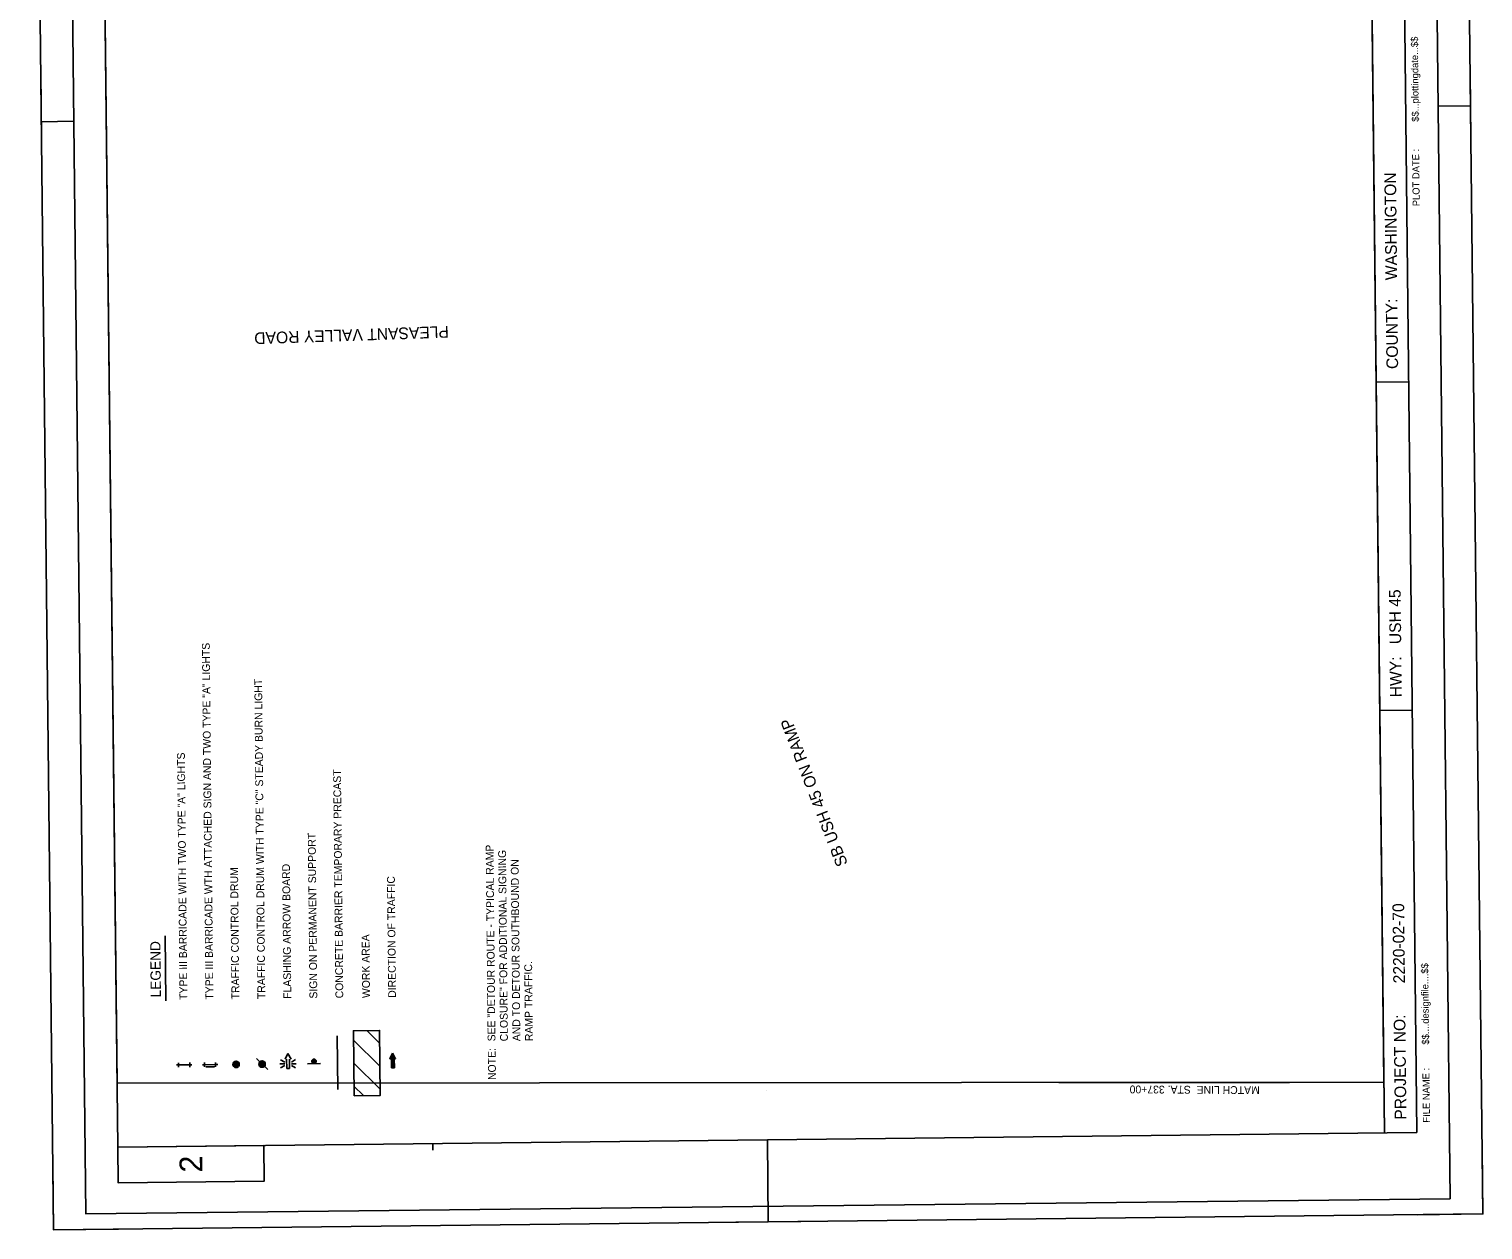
# Model space of a CAD drawing. Extents: x 359329 to 360448, y 158019 to 159731.
# Drawn here: x 359329 to 360448, y 158019 to 158943 of the extents above; entities that cross this region are included whole.
import ezdxf

# ---------------------------------------------------------------- set-up
doc = ezdxf.new("R2010")
doc.units = 0
for name, color, linetype in [('CA-MTCH-LINE', 7, 'Continuous'), ('CA-MTCH-LINE-TEXT', 7, 'Continuous'), ('Default', 7, 'Continuous'), ('Level 28', 7, 'Continuous'), ('P_Kapur_PFFE CELL [KAPUR_CADDS_LEVELS]', 7, 'Continuous'), ('P_MISC', 7, 'Continuous'), ('P_RDWY_Text', 7, 'Continuous'), ('P_TC', 7, 'Continuous'), ('P_TC_FlowArrow', 7, 'Continuous'), ('P_TC_Text', 7, 'Continuous'), ('P_TXT_Plan 1 [KAPUR_CADDS_LEVELS]', 7, 'Continuous'), ('PLT_Sheet_Info', 7, 'Continuous')]:
    doc.layers.add(name, color=color, linetype=linetype)

msp = doc.modelspace()

# ---------------------------------------------------------------- linework, layer by layer
at = {"layer": 'CA-MTCH-LINE'}
msp.add_line((360121.1, 158132.3), (360298.8, 158132.4), dxfattribs=at)
at = {"layer": 'Default'}
msp.add_lwpolyline([(359396.4, 158131.7), (360371.4, 158132.5), (360354.3, 159668.5), (359606.5, 159660.2), (359611.2, 159267.1), (359383.8, 159264.8)], close=True, dxfattribs=at)
msp.add_lwpolyline([(359396.4, 158131.7), (360371.4, 158132.5), (360354.3, 159668.5), (359606.5, 159660.2), (359611.2, 159267.1), (359383.8, 159264.8)], close=True, dxfattribs=at)
msp.add_lwpolyline([(359396.4, 158131.7), (360371.4, 158132.5), (360354.3, 159668.5), (359606.5, 159660.2), (359611.2, 159267.1), (359383.8, 159264.8)], close=True, dxfattribs=at)
at = {"layer": 'Level 28'}
for p, q in [((360371.8, 158093.6), (360354.3, 159668.5)), ((360396.8, 158093.9), (360379.3, 159668.8)), ((359396.9, 158082.7), (359379.4, 159657.6)), ((360438.3, 158858.6), (360437.8, 158908.6)), ((359338.4, 158846.4), (359337.9, 158896.4)), ((360438.1, 158883.6), (360413.1, 158883.3)), ((359338.1, 158871.4), (359363.1, 158871.7)), ((360390.4, 158671.3), (360365.4, 158671)), ((360393.2, 158418.8), (360368.2, 158418.6)), ((359896.5, 158125.8), (359896.5, 158125.8)), ((360396.8, 158093.9), (359396.9, 158082.7)), ((359639.4, 158085.4), (359639.4, 158080.4)), ((359897.6, 158025.1), (359896.9, 158088.3)), ((360447.5, 158031.2), (360447, 158081.2)), ((359347.6, 158018.9), (359347.1, 158068.9)), ((359922.6, 158025.3), (359872.6, 158024.8)), ((360447.5, 158031.2), (360397.5, 158030.6)), ((359397.6, 158019.5), (359347.6, 158018.9))]:
    msp.add_line(p, q, dxfattribs=at)
msp.add_lwpolyline([(359396.9, 158082.7), (359397.2, 158055.2), (359509.7, 158056.5), (359509.4, 158084)], close=True, dxfattribs=at)
at = {"layer": 'P_Kapur_PFFE CELL [KAPUR_CADDS_LEVELS]'}
for points in [[(360447.5, 158031.2), (360428.6, 159731.1), (359328.7, 159718.8), (359347.6, 158018.9)], [(360422.4, 158042.9), (360404, 159697.8), (359354.1, 159686.1), (359372.5, 158031.2)]]:
    msp.add_lwpolyline(points, close=True, dxfattribs=at)
at = {"layer": 'P_MISC'}
for p, q in [((359598.5, 158162.7), (359588.7, 158172.3)), ((359598.6, 158145), (359578.4, 158164.9)), ((359443.8, 158145.8), (359443.8, 158147.5)), ((359443.8, 158147.5), (359443.8, 158145.8)), ((359452.3, 158147.6), (359452.3, 158145.9)), ((359452.3, 158145.9), (359452.3, 158147.6)), ((359463.8, 158146), (359463.8, 158147.7)), ((359463.8, 158147.7), (359463.8, 158146)), ((359472.3, 158147.8), (359472.3, 158146.1)), ((359472.3, 158146.1), (359472.3, 158147.8)), ((359472.3, 158146.1), (359474, 158146.1)), ((359474, 158146.1), (359472.3, 158146.1)), ((359512.4, 158142.3), (359503.7, 158150.7)), ((359525.5, 158146.7), (359521.8, 158146.6)), ((359525.5, 158147.9), (359522.3, 158149.8)), ((359525.8, 158150.2), (359527.9, 158154.6)), ((359527, 158143.1), (359526.9, 158150.2)), ((359527.9, 158154.6), (359530.3, 158150.3)), ((359529.1, 158150.3), (359529.2, 158143.1)), ((359530.6, 158148), (359533.8, 158149.9)), ((359530.6, 158146.7), (359534.3, 158146.8)), ((359553, 158146.9), (359543, 158146.8)), ((359598.8, 158127.3), (359578.6, 158147.2)), ((359443.8, 158145.8), (359442.1, 158145.8)), ((359442.1, 158145.8), (359443.8, 158145.8)), ((359452.3, 158145.9), (359443.8, 158145.8)), ((359443.8, 158145.8), (359443.8, 158144.1)), ((359443.8, 158144.1), (359443.8, 158145.8)), ((359452.3, 158145.9), (359454, 158145.9)), ((359454, 158145.9), (359452.3, 158145.9)), ((359452.3, 158145.9), (359452.3, 158144.2)), ((359452.3, 158144.2), (359452.3, 158145.9)), ((359463.8, 158146), (359462.1, 158146)), ((359462.1, 158146), (359463.8, 158146)), ((359472.3, 158146.1), (359463.8, 158146)), ((359463.8, 158146), (359463.8, 158144.3)), ((359463.8, 158144.3), (359463.8, 158146)), ((359471.3, 158144.4), (359464.8, 158144.4)), ((359472.3, 158146.1), (359472.3, 158144.4)), ((359472.3, 158144.4), (359472.3, 158146.1)), ((359525.5, 158145.4), (359522.3, 158143.5)), ((359529.2, 158143.1), (359527, 158143.1)), ((359530.6, 158145.5), (359533.8, 158143.6)), ((359586.1, 158122.3), (359578.7, 158129.5))]:
    msp.add_line(p, q, dxfattribs=at)
msp.add_lwpolyline([(359578.8, 158122.2), (359578.3, 158172.2), (359598.4, 158172.4), (359598.9, 158122.4)], close=True, dxfattribs=at)
for centre, radius in [((359488, 158146.3), 2.5), ((359488, 158146.3), 2), ((359488, 158146.3), 1.5), ((359488, 158146.3), 1), ((359488, 158146.3), 0.5), ((359488, 158146.3), 0.25), ((359508, 158146.5), 2.5), ((359508, 158146.5), 2), ((359508, 158146.5), 1.5), ((359508, 158146.5), 1), ((359508, 158146.5), 0.5), ((359508, 158146.5), 0.25), ((359548, 158148.6), 1.75), ((359548, 158148.6), 1), ((359548, 158148.6), 0.25)]:
    msp.add_circle(centre, radius, dxfattribs=at)
at = {"layer": 'P_RDWY_Text'}
msp.add_lwpolyline([(359347.6, 158018.9), (359328.7, 159718.8), (360428.6, 159731.1), (360447.5, 158031.2)], close=True, dxfattribs=at)
at = {"layer": 'P_TC'}
for p, q in [((359608.5, 158155), (359606.3, 158150.6)), ((359606.3, 158150.6), (359610.8, 158150.6)), ((359606.6, 158150.6), (359606.6, 158151)), ((359607, 158150.6), (359607, 158151.9)), ((359607.5, 158150.6), (359607.5, 158152.8)), ((359607.5, 158143.5), (359607.5, 158150.6)), ((359608, 158143.5), (359607.9, 158153.7)), ((359608.4, 158143.5), (359608.3, 158154.6)), ((359608.5, 158155), (359610.8, 158150.6)), ((359608.9, 158143.5), (359608.8, 158154.5)), ((359609.3, 158143.5), (359609.2, 158153.6)), ((359609.7, 158150.6), (359609.7, 158152.8)), ((359609.8, 158143.5), (359609.7, 158150.6)), ((359610.2, 158150.6), (359610.2, 158151.9)), ((359610.6, 158150.7), (359610.6, 158151.1)), ((359607.5, 158143.5), (359609.8, 158143.5)), ((359608.7, 158143.5), (359608.7, 158143.5))]:
    msp.add_line(p, q, dxfattribs=at)
at = {"layer": 'P_TC_FlowArrow'}
msp.add_line((359566.3, 158126.9), (359565.8, 158168.3), dxfattribs=at)
at = {"layer": 'P_TC_Text'}
msp.add_line((359434, 158195.2), (359433.5, 158245.1), dxfattribs=at)
at = {"layer": 'P_TXT_Plan 1 [KAPUR_CADDS_LEVELS]'}
msp.add_lwpolyline([(359347.6, 158018.9), (359328.7, 159718.8), (360428.6, 159731.1), (360447.5, 158031.2), (359347.6, 158018.9)], dxfattribs=at)
at = {"layer": 'PLT_Sheet_Info'}
msp.add_lwpolyline([(360371.8, 158093.6), (360354.3, 159668.5)], dxfattribs=at)

# ---------------------------------------------------------------- texts
at = {"layer": 'CA-MTCH-LINE-TEXT'}
for s, height, rotation, p in [('PLEASANT VALLEY ROAD', 9, 181.9355, (359651.6, 158714.3)), ('SB USH 45 ON RAMP', 9, 111.2195, (359958.9, 158300.6)), ('MATCH LINE  STA. 337+00', 6, 179.6332, (360275.8, 158129.4))]:
    msp.add_text(s, height=height, rotation=rotation, dxfattribs=at).set_placement(p)
at = {"layer": 'Level 28'}
for s, height, p in [('$$...plottingdate...$$', 5.4, (360398.2, 158871.4)), ('PLOT DATE :', 5.4, (360398.9, 158806.4)), (' WASHINGTON', 9, (360381.6, 158746.2)), ('COUNTY:', 9, (360382.3, 158681.2)), (' USH 45', 9, (360384.7, 158466.2)), ('HWY:', 9, (360385.1, 158428.7)), (' 2220-02-70', 9, (360387.6, 158205.3)), ('$$....designfile....$$', 5.4, (360406.1, 158161.5)), ('PROJECT NO:', 9, (360388.7, 158103.8)), ('FILE NAME :', 5.4, (360406.8, 158101.5)), ('2', 17.5, (359462.1, 158063.2))]:
    msp.add_text(s, height=height, rotation=90.6368, dxfattribs=at).set_placement(p)
at = {"layer": 'P_TC_Text'}
for s, height, p in [('TYPE III BARRICADE WTH ATTACHED SIGN AND TWO TYPE "A" LIGHTS', 6, (359470.5, 158196.1)), ('TRAFFIC CONTROL DRUM WITH TYPE "C" STEADY BURN LIGHT', 6, (359510.5, 158196.5)), ('TYPE III BARRICADE WITH TWO TYPE "A" LIGHTS', 6, (359450.5, 158195.9)), ('CONCRETE BARRIER TEMPORARY PRECAST', 6, (359570.5, 158197.1)), ('SIGN ON PERMANENT SUPPORT', 6, (359550.5, 158196.9)), ('SEE "DETOUR ROUTE - TYPICAL RAMP', 6, (359687.6, 158164)), ('CLOSURE" FOR ADDITIONAL SIGNING', 6, (359697.2, 158164)), ('AND TO DETOUR SOUTHBOUND ON', 6, (359706.8, 158164.1)), ('TRAFFIC CONTROL DRUM', 6, (359490.5, 158196.3)), ('FLASHING ARROW BOARD', 6, (359530.5, 158196.7)), ('DIRECTION OF TRAFFIC', 6, (359611.1, 158197.5)), ('LEGEND', 7.88, (359430.2, 158197.8)), ('WORK AREA', 6, (359591.1, 158197.3)), ('RAMP TRAFFIC.', 6, (359716.4, 158164.2)), ('NOTE:', 6, (359688, 158134.3))]:
    msp.add_text(s, height=height, rotation=90.5775, dxfattribs=at).set_placement(p)

doc.saveas('drawing.dxf')
